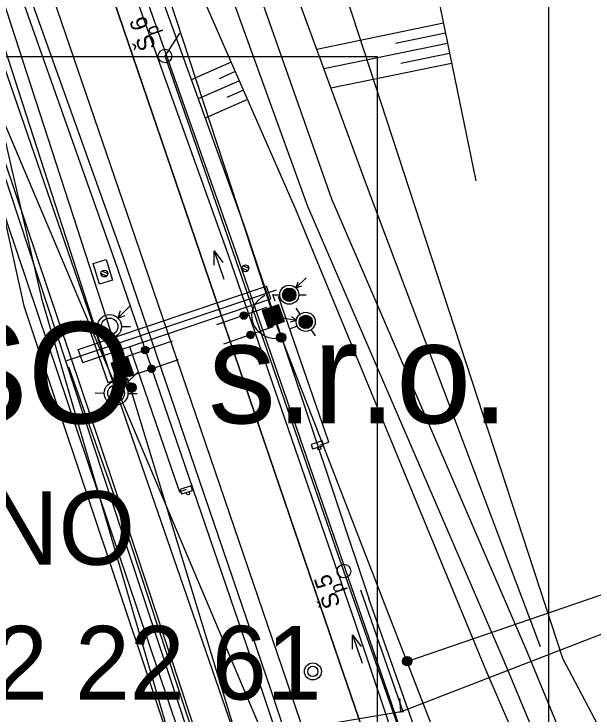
# Model space of a CAD drawing. Extents: x -439827 to -439102, y -1131353 to -1129707.
# Drawn here: x -439341.3 to -439298.8, y -1130686.6 to -1130635.3 of the extents above; entities that cross this region are included whole.
import ezdxf

# ---------------------------------------------------------------- set-up
doc = ezdxf.new("R2010")
doc.units = 0
for name, color, linetype in [('Vrstva 1', 7, 'Continuous'), ('Vrstva 10', 7, 'Continuous'), ('Vrstva 11', 7, 'Continuous'), ('Vrstva 14', 7, 'Continuous'), ('Vrstva 15', 7, 'Continuous'), ('Vrstva 2', 7, 'Continuous'), ('Vrstva 20', 7, 'Continuous'), ('Vrstva 36', 7, 'Continuous'), ('Vrstva 4', 7, 'Continuous'), ('Vrstva 42', 7, 'Continuous'), ('Vrstva 48', 7, 'Continuous'), ('Vrstva 49', 7, 'Continuous'), ('Vrstva 5', 7, 'Continuous'), ('Vrstva 57', 7, 'Continuous'), ('Vrstva 59', 7, 'Continuous'), ('Vrstva 6', 7, 'Continuous'), ('Vrstva 61', 7, 'Continuous'), ('Vrstva 62', 7, 'Continuous'), ('Vrstva 63', 7, 'Continuous'), ('Vrstva 7', 7, 'Continuous'), ('Vrstva 8', 7, 'Continuous'), ('Vrstva 9', 7, 'Continuous')]:
    doc.layers.add(name, color=color, linetype=linetype)

# ---------------------------------------------------------------- blocks, each defined once
blk = doc.blocks.new('KOTV_T')
at = {"layer": 'Vrstva 1'}
for p, q in [((-3.44, -0.33), (0.33, 3.44)), ((-3.42, 0.47), (-0.47, 3.42)), ((-3.31, -0.98), (0.98, 3.31)), ((-3.09, -1.54), (1.54, 3.09)), ((-3.06, 1.61), (-1.61, 3.06)), ((-2.8, -2.02), (2.02, 2.8)), ((-2.44, -2.44), (2.44, 2.44)), ((-2.02, -2.8), (2.8, 2.02)), ((-1.54, -3.09), (3.09, 1.54)), ((-0.98, -3.31), (3.31, 0.98)), ((-0.33, -3.44), (3.44, 0.33)), ((0.47, -3.42), (3.42, -0.47)), ((1.61, -3.06), (3.06, -1.61))]:
    blk.add_line(p, q, dxfattribs=at)
blk.add_circle((0, 0), 3.45, dxfattribs=at)
blk = doc.blocks.new('ST1K_K')
at = {"layer": 'Vrstva 1'}
for p, q in [((0, 0), (45.31, 0)), ((20.84, -3.13), (17.41, 0.3)), ((21.43, -3.01), (17.53, 0.89)), ((21.94, -2.81), (17.73, 1.4)), ((22.38, -2.55), (17.99, 1.84)), ((22.76, -2.22), (18.32, 2.22)), ((23.08, -1.84), (18.7, 2.55)), ((23.35, -1.4), (19.14, 2.81)), ((23.55, -0.89), (19.65, 3.01)), ((23.67, -0.3), (20.24, 3.13)), ((23.65, 0.42), (20.96, 3.11)), ((23.32, 1.46), (22, 2.78)), ((20.12, -3.11), (17.43, -0.42)), ((19.07, -2.78), (17.76, -1.46))]:
    blk.add_line(p, q, dxfattribs=at)
blk.add_circle((20.54, 0), 3.14, dxfattribs=at)
blk = doc.blocks.new('ST_BP')
at = {"layer": 'Vrstva 1'}
for p, q in [((7.5, 7.5), (-7.5, 7.5)), ((-7.5, 7.5), (-7.5, -7.5)), ((-7.5, -7.5), (7.5, 7.5)), ((-7.5, -7.08), (7.08, 7.5)), ((-7.5, -6.65), (6.65, 7.5)), ((-7.5, -6.23), (6.23, 7.5)), ((-7.5, -5.8), (5.8, 7.5)), ((-7.5, -5.38), (5.38, 7.5)), ((-7.5, -4.95), (4.95, 7.5)), ((-7.5, -4.53), (4.53, 7.5)), ((-7.5, -4.11), (4.11, 7.5)), ((-7.5, -3.68), (3.68, 7.5)), ((-7.5, -3.26), (3.26, 7.5)), ((-7.5, -2.83), (2.83, 7.5)), ((-7.5, -2.41), (2.41, 7.5)), ((-7.5, -1.98), (1.98, 7.5)), ((-7.5, -1.56), (1.56, 7.5)), ((-7.5, -1.14), (1.14, 7.5)), ((-7.5, -0.71), (0.71, 7.5)), ((-7.5, -0.29), (0.29, 7.5)), ((-7.5, 0.14), (-0.14, 7.5)), ((-7.5, 0.56), (-0.56, 7.5)), ((-7.5, 0.99), (-0.99, 7.5)), ((-7.5, 1.41), (-1.41, 7.5)), ((-7.5, 1.83), (-1.83, 7.5)), ((-7.5, 2.26), (-2.26, 7.5)), ((-7.5, 2.68), (-2.68, 7.5)), ((-7.5, 3.11), (-3.11, 7.5)), ((-7.5, 3.53), (-3.53, 7.5)), ((-7.5, 3.96), (-3.96, 7.5)), ((-7.5, 4.38), (-4.38, 7.5)), ((-7.5, 4.8), (-4.8, 7.5)), ((-7.5, 5.23), (-5.23, 7.5)), ((-7.5, 5.65), (-5.65, 7.5)), ((-7.5, 6.08), (-6.08, 7.5)), ((-7.5, 6.5), (-6.5, 7.5)), ((-7.5, 6.92), (-6.92, 7.5)), ((-7.5, 7.35), (-7.35, 7.5)), ((-7.08, -7.5), (7.5, 7.08)), ((-6.65, -7.5), (7.5, 6.65)), ((-6.23, -7.5), (7.5, 6.23)), ((7.5, -7.5), (7.5, 7.5)), ((-5.8, -7.5), (7.5, 5.8)), ((-5.38, -7.5), (7.5, 5.38)), ((-4.95, -7.5), (7.5, 4.95)), ((-4.53, -7.5), (7.5, 4.53)), ((-4.11, -7.5), (7.5, 4.11)), ((-3.68, -7.5), (7.5, 3.68)), ((-3.26, -7.5), (7.5, 3.26)), ((-2.83, -7.5), (7.5, 2.83)), ((-2.41, -7.5), (7.5, 2.41)), ((-1.98, -7.5), (7.5, 1.98)), ((-1.56, -7.5), (7.5, 1.56)), ((-1.14, -7.5), (7.5, 1.14)), ((-0.71, -7.5), (7.5, 0.71)), ((-0.29, -7.5), (7.5, 0.29)), ((0.14, -7.5), (7.5, -0.14)), ((0.56, -7.5), (7.5, -0.56)), ((0.99, -7.5), (7.5, -0.99)), ((1.41, -7.5), (7.5, -1.41)), ((1.83, -7.5), (7.5, -1.83)), ((2.26, -7.5), (7.5, -2.26)), ((2.68, -7.5), (7.5, -2.68)), ((3.11, -7.5), (7.5, -3.11)), ((3.53, -7.5), (7.5, -3.53)), ((3.96, -7.5), (7.5, -3.96)), ((4.38, -7.5), (7.5, -4.38)), ((4.8, -7.5), (7.5, -4.8)), ((5.23, -7.5), (7.5, -5.23)), ((5.65, -7.5), (7.5, -5.65)), ((-7.5, -7.5), (7.5, -7.5)), ((6.08, -7.5), (7.5, -6.08)), ((6.5, -7.5), (7.5, -6.5)), ((6.92, -7.5), (7.5, -6.92)), ((7.35, -7.5), (7.5, -7.35))]:
    blk.add_line(p, q, dxfattribs=at)

msp = doc.modelspace()

# ---------------------------------------------------------------- linework, layer by layer
at = {"layer": 'Vrstva 1'}
msp.add_lwpolyline([(-439827.026, -1130069.63), (-439302.026, -1130069.63), (-439302.026, -1130812.13), (-439827.026, -1130812.13)], close=True, dxfattribs=at)
at = {"layer": 'Vrstva 10'}
for p, q in [((-439309.738, -1130635.982), (-439319.036, -1130637.898)), ((-439309.588, -1130636.718), (-439313.262, -1130637.474)), ((-439309.436, -1130637.452), (-439318.514, -1130639.322)), ((-439309.286, -1130638.186), (-439312.872, -1130638.926)), ((-439325.316, -1130638.834), (-439328.242, -1130640.118)), ((-439309.134, -1130638.922), (-439317.992, -1130640.746)), ((-439325.014, -1130639.522), (-439326.204, -1130640.044)), ((-439324.712, -1130640.21), (-439327.732, -1130641.534)), ((-439324.412, -1130640.896), (-439325.636, -1130641.434)), ((-439324.11, -1130641.582), (-439327.22, -1130642.946))]:
    msp.add_line(p, q, dxfattribs=at)
at = {"layer": 'Vrstva 11'}
for points in [[(-439303.556, -1130682.146), (-439317.916, -1130648.878), (-439327.804, -1130620.82), (-439331.376, -1130615.792)], [(-439331.216, -1130618.836), (-439329.76, -1130621.648), (-439319.704, -1130649.398), (-439305.298, -1130682.74)], [(-439290.368, -1130714.13), (-439303.556, -1130682.146)], [(-439305.298, -1130682.74), (-439291.93, -1130714.86)]]:
    msp.add_lwpolyline(points, dxfattribs=at)
at = {"layer": 'Vrstva 14'}
msp.add_lwpolyline([(-439335.44, -1130653.596), (-439334.502, -1130653.304), (-439334.034, -1130654.828), (-439334.97, -1130655.116), (-439335.44, -1130653.596)], dxfattribs=at)
at = {"layer": 'Vrstva 15'}
for p, q in [((-439324.102, -1130654.142), (-439324.512, -1130653.94)), ((-439324.016, -1130653.974), (-439324.432, -1130653.77)), ((-439334.46, -1130654.528), (-439334.87, -1130654.328)), ((-439334.374, -1130654.362), (-439334.79, -1130654.158))]:
    msp.add_line(p, q, dxfattribs=at)
for centre in [(-439334.622, -1130654.34), (-439324.264, -1130653.954)]:
    msp.add_circle(centre, 0.25, dxfattribs=at)
at = {"layer": 'Vrstva 2'}
for centre, radius, start, end in [((-439322.18, -1130657.459), 1.636, 113.691, 198.3072), ((-439322.18, -1130657.459), 1.636, 113.691, 198.3072), ((-439321.987, -1130657.207), 1.907, 203.6959, 268.8931), ((-439321.987, -1130657.207), 1.907, 203.6959, 268.8931)]:
    msp.add_arc(centre, radius, start, end, dxfattribs=at)
at = {"layer": 'Vrstva 20'}
for points in [[(-439321.24, -1130684.25), (-439331.724, -1130653.514), (-439341.682, -1130624.428), (-439343.148, -1130620.102), (-439344.652, -1130615.74), (-439353.044, -1130591.112), (-439364.316, -1130558.138), (-439374.988, -1130526.952), (-439385.508, -1130496.17), (-439396.186, -1130464.956), (-439407.226, -1130432.678), (-439417.232, -1130403.478), (-439427.682, -1130373.028), (-439438.464, -1130341.588), (-439448.942, -1130311.012), (-439450.914, -1130305.246), (-439460.972, -1130277.082), (-439482.918, -1130211.888), (-439494.254, -1130178.768), (-439505.592, -1130145.672), (-439514.996, -1130118.198), (-439526.684, -1130084.16)], [(-439317.356, -1130682.842), (-439326.906, -1130654.872), (-439337.798, -1130622.974), (-439339.224, -1130618.794), (-439340.706, -1130614.468), (-439349.146, -1130589.75), (-439360.302, -1130557.13), (-439371.172, -1130525.358), (-439381.62, -1130494.81), (-439392.342, -1130463.488), (-439403.314, -1130431.488), (-439413.424, -1130401.962), (-439423.826, -1130371.538), (-439434.464, -1130340.548), (-439445.064, -1130309.558), (-439445.462, -1130308.388), (-439447.35, -1130302.89), (-439457.16, -1130275.562), (-439478.968, -1130210.544), (-439490.24, -1130177.636), (-439501.606, -1130144.528), (-439511.068, -1130116.958), (-439519.726, -1130091.71)], [(-439269.22, -1130818.812), (-439281.814, -1130783.396), (-439292.526, -1130753.502), (-439304.678, -1130719.318), (-439314.858, -1130690.108), (-439317.356, -1130682.842)], [(-439274.97, -1130820.588), (-439286.854, -1130785.132), (-439297.084, -1130755.104), (-439308.786, -1130720.798), (-439319.098, -1130690.52), (-439321.24, -1130684.25)]]:
    msp.add_lwpolyline(points, dxfattribs=at)
at = {"layer": 'Vrstva 36'}
for p, q in [((-439322.55, -1130616.62), (-439300.99, -1130682.56)), ((-439323.66, -1130704.2), (-439346.85, -1130635.55)), ((-439300.99, -1130682.56), (-439292.55, -1130698.49))]:
    msp.add_line(p, q, dxfattribs=at)
at = {"layer": 'Vrstva 4'}
for points in [[(-439316.204, -1130679.942), (-439325.518, -1130652.992), (-439336.244, -1130623.018), (-439338.082, -1130617.638)], [(-439315.982, -1130678.73), (-439324.99, -1130652.666), (-439335.578, -1130622.688), (-439337.526, -1130617.51)], [(-439322.95, -1130685.206), (-439333.858, -1130653.394), (-439343.59, -1130625.92), (-439345.752, -1130619.412)], [(-439322.368, -1130684.93), (-439333.25, -1130653.118), (-439343.108, -1130625.602), (-439345.194, -1130619.284)], [(-439280.01, -1130783.522), (-439290.374, -1130752.75), (-439302.642, -1130717.624), (-439315.982, -1130678.73)], [(-439280.01, -1130783.522), (-439291.102, -1130753.178), (-439303.358, -1130718.188), (-439316.204, -1130679.942)], [(-439237.656, -1130937.666), (-439241, -1130926.51), (-439249.718, -1130901.172), (-439258.406, -1130875.05), (-439266.76, -1130849.346), (-439276.348, -1130820.732), (-439289.274, -1130782.246), (-439298.276, -1130755.542), (-439309.968, -1130722.042), (-439322.368, -1130684.93)], [(-439237.656, -1130937.666), (-439241.95, -1130926.674), (-439250.188, -1130901.72), (-439259.018, -1130875.526), (-439267.634, -1130849.508), (-439276.91, -1130821.49), (-439290.192, -1130781.67), (-439298.758, -1130756.05), (-439310.466, -1130722.552), (-439322.95, -1130685.206)]]:
    msp.add_lwpolyline(points, dxfattribs=at)
at = {"layer": 'Vrstva 42'}
for points in [[(-439395.105, -1130455.427), (-439392.342, -1130463.488), (-439381.62, -1130494.81), (-439371.172, -1130525.358), (-439360.302, -1130557.13), (-439349.146, -1130589.75), (-439340.706, -1130614.468), (-439339.224, -1130618.794), (-439337.798, -1130622.974), (-439326.906, -1130654.872), (-439317.356, -1130682.842)], [(-439321.24, -1130684.25), (-439331.724, -1130653.514), (-439341.682, -1130624.428), (-439343.148, -1130620.102), (-439344.652, -1130615.74), (-439353.044, -1130591.112), (-439364.316, -1130558.138), (-439374.988, -1130526.952), (-439385.508, -1130496.17), (-439396.186, -1130464.956), (-439399.158, -1130456.267)], [(-439317.356, -1130682.842), (-439314.858, -1130690.108), (-439304.678, -1130719.318), (-439294.356, -1130748.353)], [(-439299.143, -1130749.065), (-439308.786, -1130720.798), (-439319.098, -1130690.52), (-439321.24, -1130684.25)]]:
    msp.add_lwpolyline(points, dxfattribs=at)
at = {"layer": 'Vrstva 48'}
msp.add_line((-439330.171, -1130638.383), (-439329.092, -1130636.695), dxfattribs=at)
msp.add_lwpolyline([(-439273.977, -1130800.586), (-439287.398, -1130761.145), (-439303.815, -1130713.917), (-439317.04, -1130676.167), (-439330.171, -1130638.383)], dxfattribs=at)
for centre in [(-439330.171, -1130638.383), (-439317.04, -1130676.167)]:
    msp.add_circle(centre, 0.5, dxfattribs=at)
at = {"layer": 'Vrstva 49'}
for p, q in [((-439326.571, -1130652.681), (-439325.854, -1130654.756)), ((-439316.418, -1130680.852), (-439315.701, -1130682.928))]:
    msp.add_line(p, q, dxfattribs=at)
for points in [[(-439326.552, -1130653.732), (-439326.571, -1130652.681), (-439325.937, -1130653.52)], [(-439316.399, -1130681.904), (-439316.418, -1130680.852), (-439315.785, -1130681.691)]]:
    msp.add_lwpolyline(points, dxfattribs=at)
at = {"layer": 'Vrstva 5'}
msp.add_lwpolyline([(-439277.797, -1130823.31), (-439296.36, -1130772.17), (-439314.646, -1130718.277), (-439334.211, -1130661.631), (-439352.883, -1130603.988)], dxfattribs=at)
at = {"layer": 'Vrstva 57'}
for p, q in [((-439300.573, -1130713.355), (-439321.952, -1130658.15)), ((-439315.693, -1130718.482), (-439332.927, -1130662.012)), ((-439312.411, -1130682.787), (-439281.025, -1130672.03))]:
    msp.add_line(p, q, dxfattribs=at)
at = {"layer": 'Vrstva 59'}
for p, q in [((-439322.958, -1130688.178), (-439346.578, -1130632.414)), ((-439315.822, -1130677.544), (-439312.712, -1130686.468)), ((-439312.712, -1130686.468), (-439322.958, -1130688.178))]:
    msp.add_line(p, q, dxfattribs=at)
msp.add_lwpolyline([(-439240.615, -1130935.08), (-439245.006, -1130936.575), (-439254.477, -1130905.195), (-439274.831, -1130847.058), (-439298.026, -1130780.807), (-439307.773, -1130752.965), (-439314.372, -1130732.153), (-439325.758, -1130696.243), (-439342.929, -1130644.213), (-439353.367, -1130615.721)], dxfattribs=at)
at = {"layer": 'Vrstva 6'}
for p, q in [((-439312.884, -1130686.484), (-439276.288, -1130672.354)), ((-439312.972, -1130685.498), (-439312.884, -1130686.484)), ((-439313.134, -1130686.506), (-439312.636, -1130686.462))]:
    msp.add_line(p, q, dxfattribs=at)
at = {"layer": 'Vrstva 61'}
for p, q in [((-439322.281, -1130657.205), (-439341.23, -1130599.505)), ((-439352.156, -1130603.174), (-439333.292, -1130661.29))]:
    msp.add_line(p, q, dxfattribs=at)
at = {"layer": 'Vrstva 62'}
msp.add_line((-439334.327, -1130661.321), (-439354.141, -1130603.913), dxfattribs=at)
at = {"layer": 'Vrstva 63'}
for p, q in [((-439337.379, -1130660.728), (-439322, -1130655.537)), ((-439336.54, -1130659.917), (-439322.722, -1130655.253)), ((-439322.397, -1130656.198), (-439322.722, -1130655.253)), ((-439321.46, -1130655.63), (-439320.64, -1130655.63)), ((-439321.41, -1130655.565), (-439320.689, -1130655.565)), ((-439321.328, -1130655.499), (-439320.771, -1130655.499)), ((-439321.214, -1130655.434), (-439320.886, -1130655.434)), ((-439322.094, -1130656.36), (-439322.257, -1130655.887)), ((-439318.154, -1130666.701), (-439321.84, -1130656.011)), ((-439321.541, -1130655.893), (-439320.558, -1130655.893)), ((-439321.525, -1130655.827), (-439320.575, -1130655.827)), ((-439321.525, -1130655.958), (-439320.575, -1130655.958)), ((-439321.509, -1130655.761), (-439320.591, -1130655.761)), ((-439321.509, -1130656.024), (-439320.591, -1130656.024)), ((-439321.492, -1130655.696), (-439320.608, -1130655.696)), ((-439321.492, -1130656.089), (-439320.608, -1130656.089)), ((-439321.46, -1130656.155), (-439320.64, -1130656.155)), ((-439336.192, -1130660.855), (-439322.397, -1130656.198)), ((-439321.41, -1130656.22), (-439320.689, -1130656.22)), ((-439321.328, -1130656.286), (-439320.771, -1130656.286)), ((-439321.214, -1130656.351), (-439320.886, -1130656.351)), ((-439319.823, -1130658.367), (-439320.293, -1130657.696)), ((-439319.751, -1130658.357), (-439320.258, -1130657.632)), ((-439319.687, -1130658.332), (-439320.214, -1130657.581)), ((-439319.624, -1130658.308), (-439320.169, -1130657.53)), ((-439319.561, -1130658.284), (-439320.125, -1130657.479)), ((-439319.517, -1130658.233), (-439320.062, -1130657.455)), ((-439319.473, -1130658.182), (-439319.999, -1130657.431)), ((-439319.428, -1130658.131), (-439319.936, -1130657.406)), ((-439319.394, -1130658.067), (-439319.863, -1130657.396)), ((-439319.368, -1130657.989), (-439319.782, -1130657.398)), ((-439319.361, -1130657.884), (-439319.681, -1130657.428)), ((-439319.373, -1130657.753), (-439319.561, -1130657.484)), ((-439321.029, -1130658.386), (-439320.434, -1130658.181)), ((-439320.006, -1130658.335), (-439320.325, -1130657.879)), ((-439319.905, -1130658.365), (-439320.318, -1130657.774)), ((-439320.125, -1130658.279), (-439320.313, -1130658.01)), ((-439335.649, -1130658.654), (-439335.093, -1130658.462)), ((-439336.192, -1130660.855), (-439336.54, -1130659.917)), ((-439334.379, -1130662.341), (-439333.793, -1130662.139)), ((-439318.797, -1130666.923), (-439318.154, -1130666.701))]:
    msp.add_line(p, q, dxfattribs=at)
for points in [[(-439279.55, -1130829.627), (-439292.524, -1130791.32), (-439307.367, -1130752.78), (-439315.541, -1130727.251), (-439322.482, -1130704.449), (-439333.14, -1130672.167), (-439347.586, -1130629.381), (-439352.159, -1130615.872), (-439360.579, -1130591.518), (-439378.343, -1130536.883)], [(-439319.821, -1130654.664), (-439320.557, -1130655.399)], [(-439320.421, -1130654.983), (-439320.557, -1130655.399)], [(-439320.557, -1130655.399), (-439320.141, -1130655.244)], [(-439322.289, -1130655.893), (-439321.746, -1130655.893)], [(-439320.354, -1130655.893), (-439319.811, -1130655.893)], [(-439332.705, -1130656.685), (-439333.625, -1130657.605)], [(-439333.455, -1130657.084), (-439333.625, -1130657.605)], [(-439320.243, -1130657.311), (-439320.554, -1130656.867)], [(-439333.625, -1130657.605), (-439333.105, -1130657.41)], [(-439321.555, -1130657.58), (-439320.53, -1130657.76)], [(-439320.53, -1130657.76), (-439320.896, -1130657.509)], [(-439335.79, -1130658.221), (-439335.112, -1130658.221)], [(-439333.371, -1130658.221), (-439332.693, -1130658.221)], [(-439320.949, -1130657.888), (-439320.53, -1130657.76)], [(-439335.649, -1130658.654), (-439334.379, -1130662.341)], [(-439319.133, -1130658.896), (-439319.444, -1130658.452)], [(-439332.774, -1130659.701), (-439329.416, -1130669.439), (-439329.105, -1130670.34), (-439328.594, -1130670.164)], [(-439229.706, -1130961.083), (-439234.319, -1130947.462), (-439238.472, -1130936.844), (-439247.924, -1130921.561), (-439263.264, -1130880.523), (-439279.451, -1130829.598), (-439292.591, -1130791.38), (-439307.551, -1130752.883), (-439315.726, -1130727.354), (-439322.667, -1130704.552), (-439333.324, -1130672.27), (-439337.219, -1130661.201)], [(-439332.196, -1130661.609), (-439333.132, -1130662.512)], [(-439332.953, -1130661.995), (-439333.132, -1130662.512)], [(-439333.132, -1130662.512), (-439332.608, -1130662.327)], [(-439335.307, -1130663.091), (-439334.629, -1130663.103)], [(-439332.889, -1130663.133), (-439332.211, -1130663.145)]]:
    msp.add_lwpolyline(points, dxfattribs=at)
for points in [[(-439319.338, -1130667.202), (-439318.524, -1130666.942), (-439318.626, -1130666.622), (-439319.44, -1130666.882)], [(-439328.971, -1130670.503), (-439328.157, -1130670.243), (-439328.259, -1130669.923), (-439329.073, -1130670.182)]]:
    msp.add_lwpolyline(points, close=True, dxfattribs=at)
for centre, radius in [((-439321.05, -1130655.893), 0.701), ((-439321.05, -1130655.893), 0.492), ((-439319.843, -1130657.882), 0.701), ((-439334.241, -1130658.221), 0.87), ((-439334.241, -1130658.221), 0.614), ((-439319.843, -1130657.882), 0.492), ((-439333.759, -1130663.118), 0.87), ((-439333.759, -1130663.118), 0.614), ((-439318.848, -1130667.167), 0.114), ((-439328.481, -1130670.468), 0.114)]:
    msp.add_circle(centre, radius, dxfattribs=at)
at = {"layer": 'Vrstva 7'}
msp.add_line((-439324.748, -1130685.414), (-439324.764, -1130685.366), dxfattribs=at)
for centre, radius in [((-439319.32, -1130683.522), 0.623), ((-439319.32, -1130683.522), 0.376), ((-439324.757, -1130685.39), 0.25)]:
    msp.add_circle(centre, radius, dxfattribs=at)
at = {"layer": 'Vrstva 8'}
for p in [(-439688.772, -1130638.427), (-439314.571, -1130801.083)]:
    msp.add_line(p, (-439314.563, -1130638.406), dxfattribs=at)
at = {"layer": 'Vrstva 9'}
for points in [[(-439302.616, -1130681.722), (-439315.394, -1130647.836), (-439325.592, -1130620.022), (-439330.646, -1130613.072), (-439326.982, -1130606.17), (-439310.098, -1130596.386)], [(-439304.064, -1130603.548), (-439312.168, -1130612.528), (-439313.262, -1130618.886), (-439307.358, -1130647.542)], [(-439337.526, -1130617.51), (-439334.41, -1130623.048), (-439324.342, -1130650.912), (-439315.202, -1130678.168)], [(-439337.526, -1130617.51), (-439332.438, -1130622.598), (-439320.59, -1130649.608), (-439306.658, -1130683.374)], [(-439329.016, -1130691.134), (-439339.192, -1130656.276), (-439343.888, -1130636.026), (-439354.284, -1130638.834)], [(-439353.788, -1130640.606), (-439344.68, -1130638.07), (-439340.524, -1130656.706), (-439329.016, -1130691.134)], [(-439225.732, -1130933.398), (-439229.604, -1130923.888), (-439239.092, -1130898.916), (-439247.79, -1130873.56), (-439257.606, -1130845.04), (-439266.65, -1130817.146), (-439278.574, -1130785.616), (-439289.83, -1130752.464), (-439300.562, -1130719.612), (-439315.202, -1130678.168)], [(-439306.658, -1130683.374), (-439292.824, -1130715.24)]]:
    msp.add_lwpolyline(points, dxfattribs=at)

# ---------------------------------------------------------------- block references
at = {"layer": 'Vrstva 2'}
for name, p, xscale, yscale, rotation in [('ST1K_K', (-439322.729, -1130656.839), 0.08533299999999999, 0.08533300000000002, -160.83699069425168), ('ST1K_K', (-439322.729, -1130656.839), 0.08533299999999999, 0.08533300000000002, -160.83699069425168), ('ST_BP', (-439322.236, -1130657.456), 0.085333, 0.08533300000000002, -160.83370949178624), ('ST_BP', (-439322.236, -1130657.456), 0.085333, 0.08533300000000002, -160.83370949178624), ('ST1K_K', (-439322.236, -1130658.256), 0.08533300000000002, 0.08533300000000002, -160.83037784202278), ('ST1K_K', (-439322.236, -1130658.256), 0.08533300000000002, 0.08533300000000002, -160.83037784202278), ('ST1K_K', (-439333.289, -1130660.521), 0.08533300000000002, 0.085333, 18.917487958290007), ('ST1K_K', (-439333.289, -1130660.521), 0.08533300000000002, 0.085333, 18.917487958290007), ('ST_BP', (-439333.305, -1130661.313), 0.085333, 0.085333, 18.91748967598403), ('ST_BP', (-439333.305, -1130661.313), 0.085333, 0.085333, 18.91748967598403), ('ST1K_K', (-439332.829, -1130661.893), 0.085333, 0.08533300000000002, 18.91748795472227), ('ST1K_K', (-439332.829, -1130661.893), 0.085333, 0.08533300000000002, 18.91748795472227)]:
    msp.add_blockref(name, p, dxfattribs=dict(at, xscale=xscale, yscale=yscale, rotation=rotation))
at = {"layer": 'Vrstva 57', "xscale": 0.10000000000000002, "yscale": 0.1, "rotation": 1}
for p in [(-439321.647, -1130659.036), (-439332.632, -1130662.706), (-439312.389, -1130682.777)]:
    msp.add_blockref('KOTV_T', p, dxfattribs=at)

# ---------------------------------------------------------------- texts
at = {"layer": 'Vrstva 49'}
for s, height, p in [('Š 6', 1.25, (-439330.824, -1130637.745)), ('p', 0.938, (-439330.545, -1130636.703)), ('Š 5', 1.25, (-439317.278, -1130678.664)), ('p', 0.938, (-439316.999, -1130677.622))]:
    msp.add_text(s, height=height, rotation=108.9175, dxfattribs=at).set_placement(p)
at = {"layer": 'Vrstva 8'}
for s, height, p in [('AGROPROJEKT PSO  s.r.o.', 7.42447, (-439431.267, -1130665.318)), ('Slavíčkova 1b, 638 00 BRNO', 5.39947, (-439426.283, -1130675.704)), ('Tel. 54522 22 58   Fax 545 22 22 61', 5.39992, (-439435.12, -1130685.586))]:
    msp.add_text(s, height=height, rotation=0.0006, dxfattribs=at).set_placement(p)

doc.saveas('drawing.dxf')
